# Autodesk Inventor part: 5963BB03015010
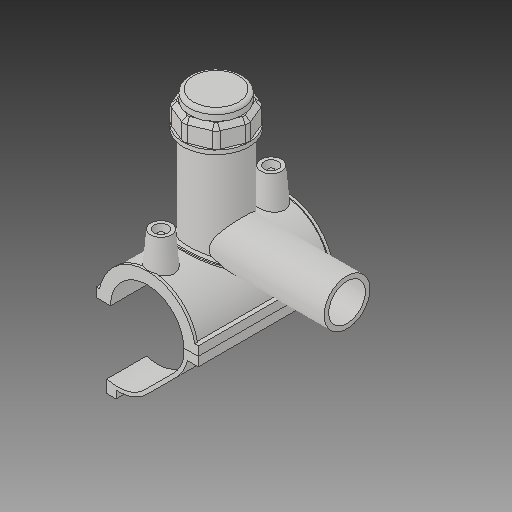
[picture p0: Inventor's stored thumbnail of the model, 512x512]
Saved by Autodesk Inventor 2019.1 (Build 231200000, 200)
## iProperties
Created: 2017-07
Part Number: 5963BB03015010
Material: Generic
Description: PLASSON TAPPING SADDLE 1 1/2''IPS x 1''IPS
Document SubType Name: Modeling
Designer: KIM
Mass: 1712.7 g
Surface Area: 2671.49 cm^2
Volume: 1712.7 cm^3
Density: 1 g/cm^3
Appearance: Default
Author: KIM
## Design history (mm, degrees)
derived "5963B.ipt"
feature "Solid1::5963B.ipt"
feature "Solid2::5963B.ipt"
feature "Solid4::5963B.ipt"
feature "Solid5::5963B.ipt"
tag "TaggingFeature1"
body "Solid1"
body "Solid2"
other parameters: "d0" = 53.1, "d2" = 74.168, "d3" = 13.275, "d4" = 100.076, "d5" = 0, "d6" = 0.1, "d8" = 0, "d19" = 6, "d20" = 6, "d21" = 60.0456, "d23" = 0, "d24" = 30.0228, "d26" = 0, "d29" = 3, "d30" = 17.7, "d31" = 6, "d32" = 0, "d33" = 0, "d34" = 0.6, "d40" = 35.8956, "d41" = 47.79, "d43" = 0, "d45" = 0, "d47" = 94.5606, "d70" = 15, "d72" = 0, "d73" = 6, "d75" = 5, "d76" = 0, "d77" = 2.655, "d78" = 56.55, "d79" = 15, "d80" = 40.0304, "d82" = 5 deg, "d84" = 4, "d85" = 14, "d86" = 0, "d87" = 3, "d88" = 0, "d89" = 1, "d90" = 1, "d91" = 80.0608, "d92" = 0, "d93" = 0.5, "d94" = 27.94737, "d96" = 70.4106, "d97" = 2.00152, "d98" = 0, "d102" = 0.531, "d120" = 140 deg, "d121" = 24.228, "d122" = 20 deg, "d123" = 138.06, "d124" = 41.418, "d126" = 0, "d143" = 54.693, "d145" = 12.25385, "d149" = 0.7965, "d150" = 13.47923, "d153" = 100.076, "d154" = 0, "d156" = 34.515, "d157" = 160 deg, "d159" = 3.186, "d161" = 0.7965, "d162" = 60.0456, "d163" = 0, "d164" = 26.55, "d167" = 5.31, "d168" = 33.67317, "d170" = 3.2805, "d172" = 0, "d173" = 1, "d175" = 26.55, "d176" = 20 deg, "d177" = 3.717, "d178" = 15.93, "d180" = 0, "d183" = 6.372, "d184" = 2.9736, "d185" = 32.5247, "d186" = 32.5247, "d187" = 34.515, "d188" = 4.779, "d189" = 3.717, "d190" = 0, "d191" = 51.7725, "d193" = 6.1236, "d194" = 3.50266, "d195" = 90 deg, "d197" = 0, "d199" = 0, "d200" = 7.965, "d202" = 0, "d203" = 98.044, "d204" = 45.4005, "d205" = 33.453, "d206" = 40.6215, "d207" = 73.533, "d208" = 76.47432, "d209" = 91.18092, "d210" = 41.0994, "d211" = 47.79, "d212" = 38.232, "d213" = -4.698, "d216" = 0, "d217" = 5.31, "d218" = 2.655, "d219" = 0.531, "d222" = 53.1, "d224" = 0, "d230" = 3.186, "d233" = 6, "d236" = 37.084, "d237" = 30.0228, "d238" = 6.02433, "d240" = 30.0228, "d241" = 30.0228, "d242" = 30.0228, "d243" = 6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
